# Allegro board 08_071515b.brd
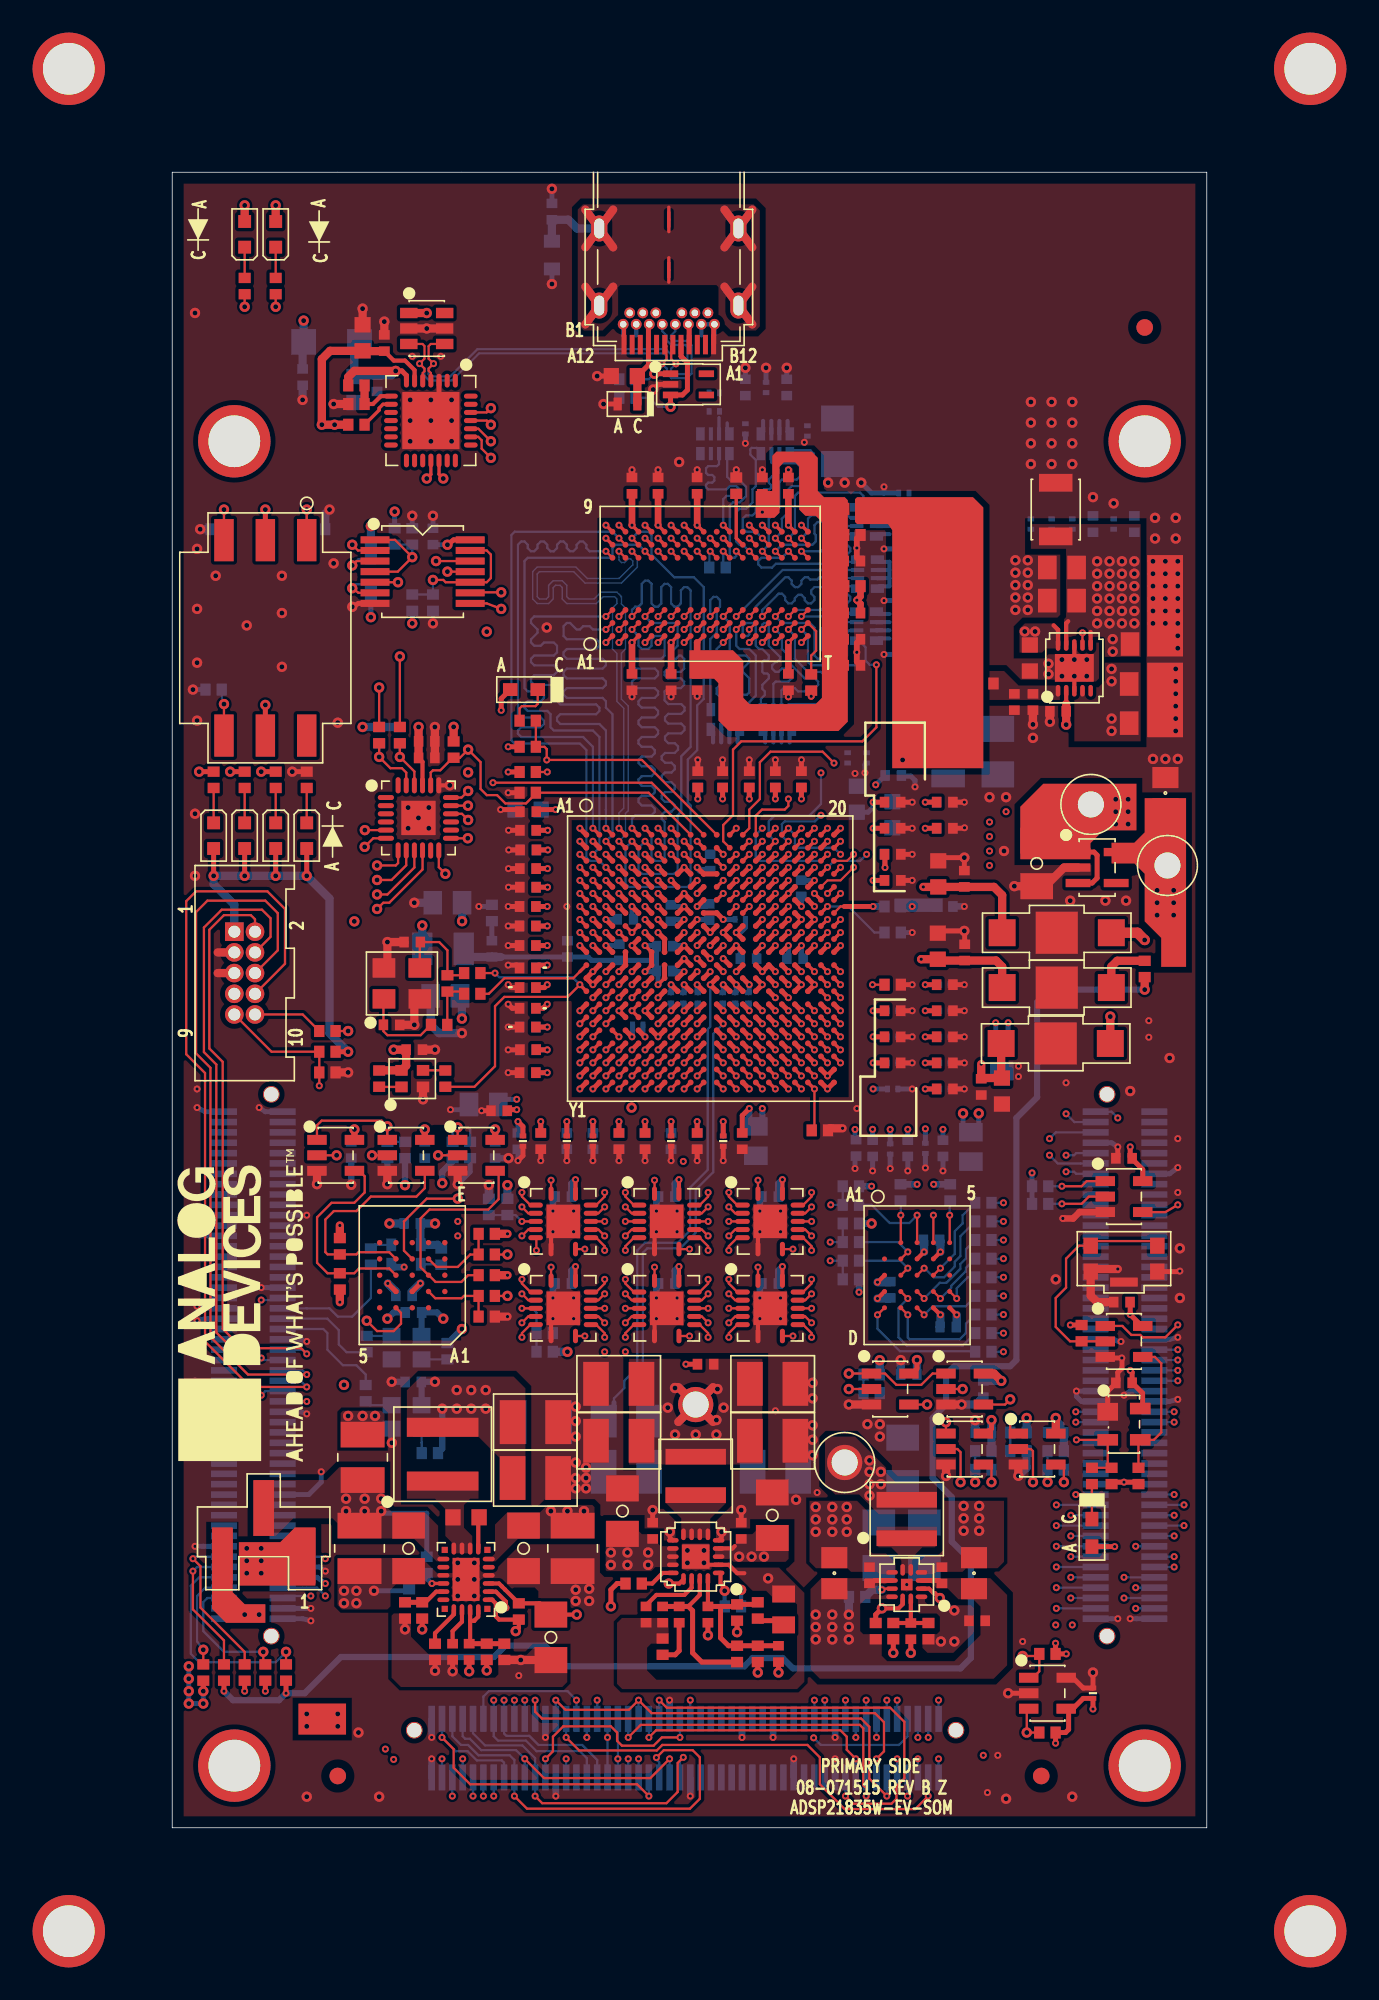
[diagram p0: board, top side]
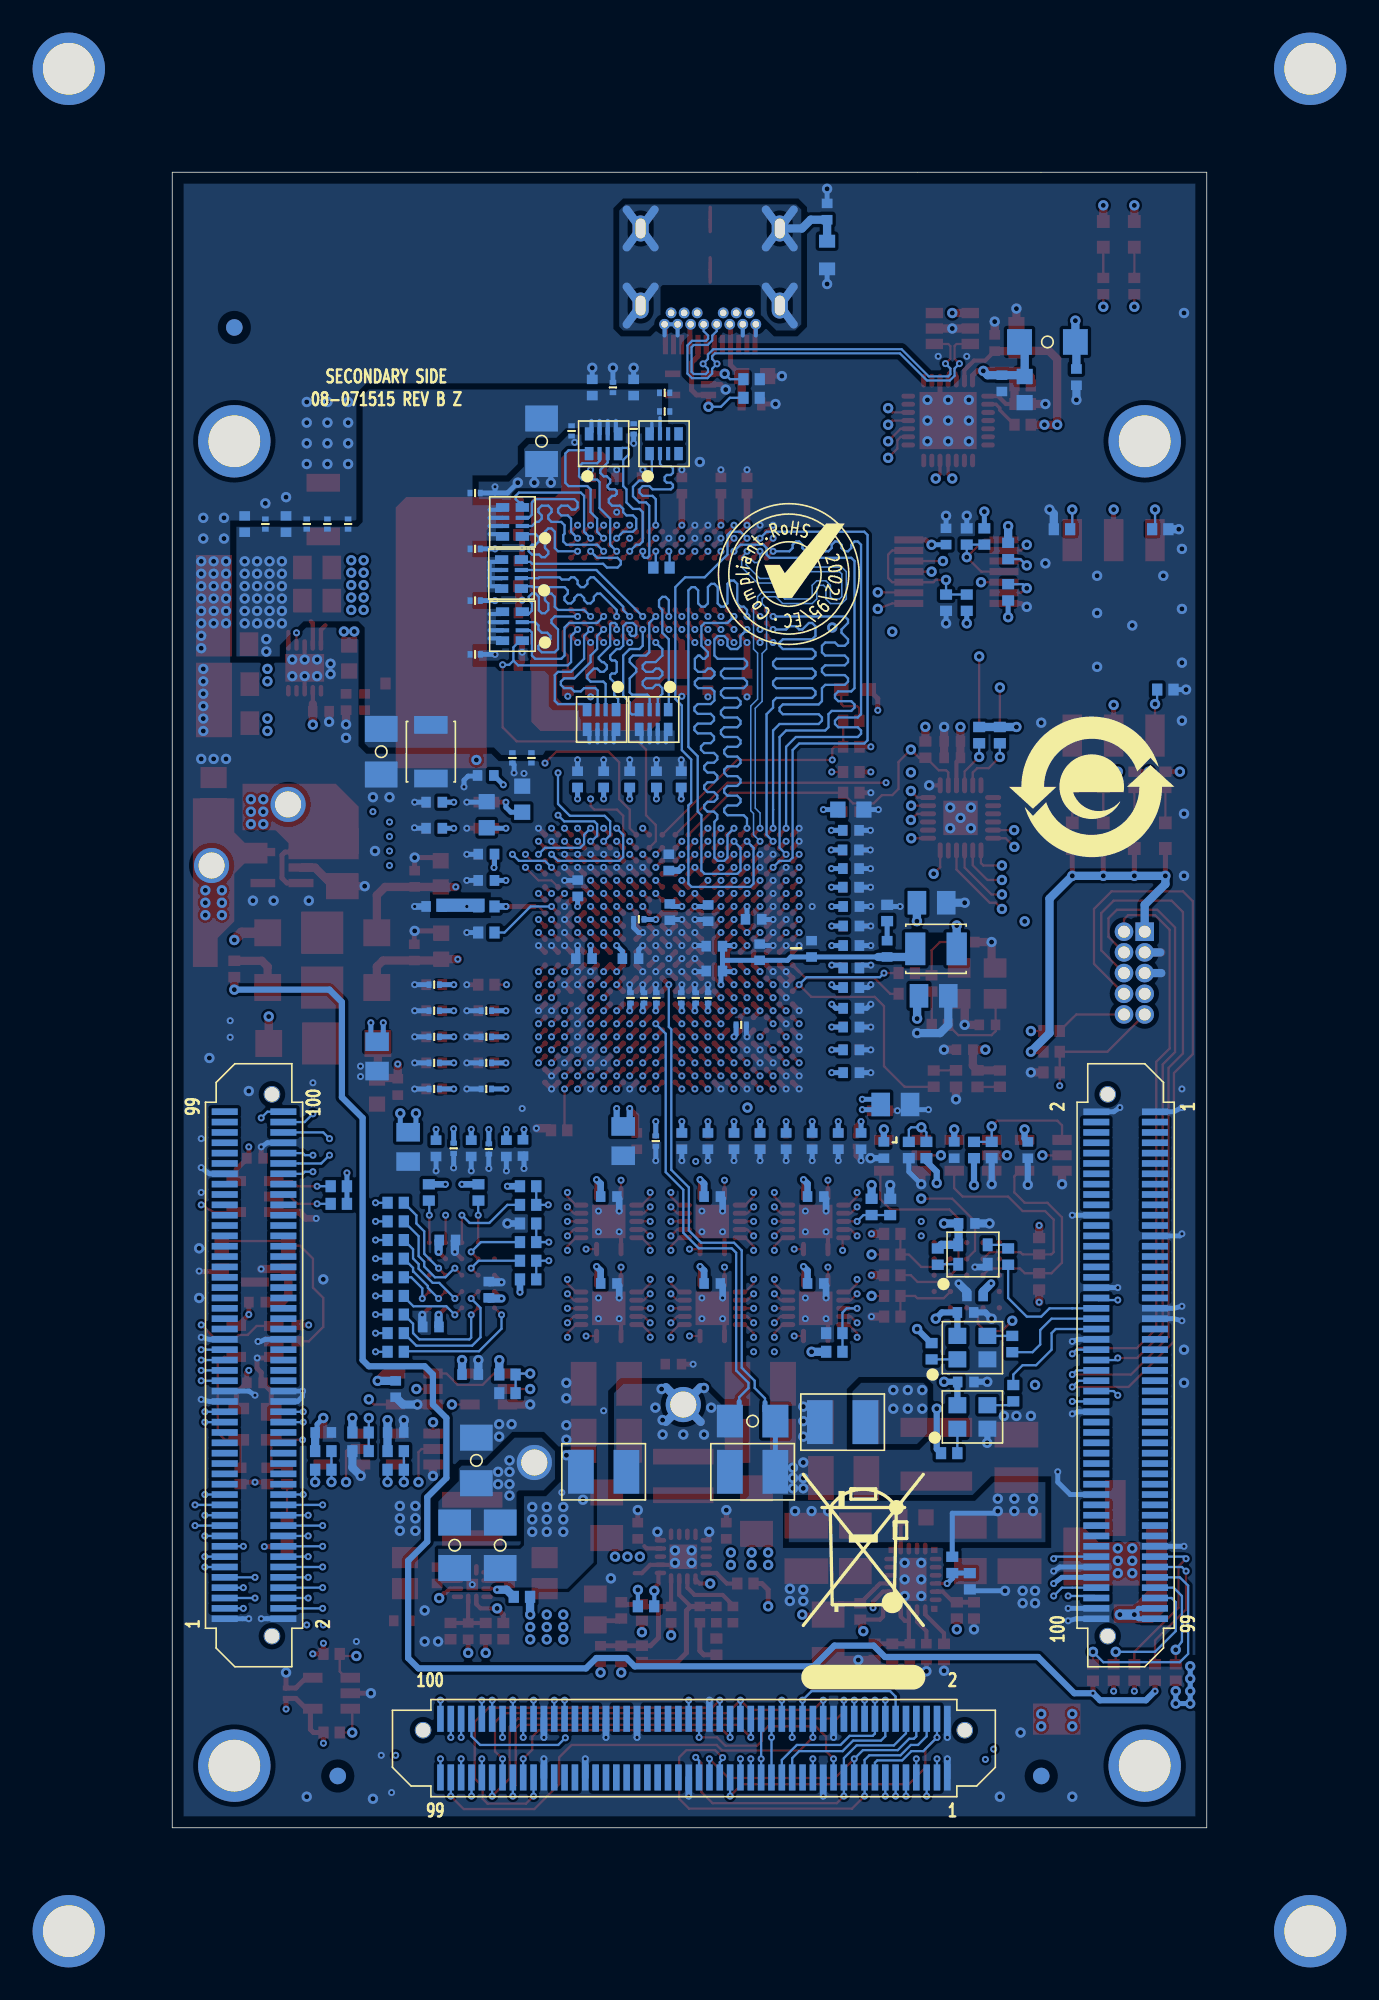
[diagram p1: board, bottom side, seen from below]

Outline 63.5 x 101.6 mm; copper layers: TOP, L2_PWR, L3_GND, L4_SIG, L5_SIG, L6_PWR, L7_SIG, L8_SIG, L9_GND, BOTTOM. Coordinates in mm from the lower left corner of the outline.
Outline path: 0,101.6 0,0 63.5,0 63.5,101.6 0,101.6

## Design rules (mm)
constraint set DEFAULT: min track width 0.14
net group DP_USB: nets USB_DM USB_DP
net group ADDRESS: nets DMC0_A00 DMC0_A01 DMC0_A02 DMC0_A03 DMC0_A04 DMC0_A05 DMC0_A06 DMC0_A07 DMC0_A08 DMC0_A09 DMC0_A10 DMC0_A11 DMC0_A12 DMC0_A13 DMC0_A14 DMC0_A15 DMC0_BA0 DMC0_BA1 DMC0_BA2 DMC0_CAS* DMC0_CKE DMC0_CS0* DMC0_ODT DMC0_RAS* DMC0_RESET* DMC0_WE*
net group DIGITAL: nets DMC0_CK DMC0_CK* DMC0_DQ00 DMC0_DQ01 DMC0_DQ02 DMC0_DQ03 DMC0_DQ04 DMC0_DQ05 DMC0_DQ06 DMC0_DQ07 DMC0_DQ08 DMC0_DQ09 DMC0_DQ10 DMC0_DQ11 DMC0_DQ12 DMC0_DQ13 DMC0_DQ14 DMC0_DQ15 DMC0_LDM DMC0_LDQS DMC0_LDQS* DMC0_UDM DMC0_UDQS DMC0_UDQS*

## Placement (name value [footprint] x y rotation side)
C1  0.1uF  [C0402]  28.22 82.37 90 top
C2  0.1uF  [C0402]  32.22 82.37 90 top
C3  0.1uF  [C0402]  37.82 82.37 90 top
C4  100pF  [C0402]  47.42 56.54 0 bottom
C5  0.1uF  [C0402]  29.82 82.37 90 top
C6  0.1uF  [C0402]  28.22 70.31 270 top
C7  0.1uF  [C0402]  30.62 70.31 270 top
C8  0.1uF  [C0402]  37.82 70.31 270 top
C9  0.01uF  [C0201]  44.91 81.92 180 bottom
C10  0.01uF  [C0201]  35.18 85.85 270 bottom
C11  10uF  [C0805H55]  59.64 67.79 0 top
C12  0.01uF  [C0201]  42.62 65.66 270 bottom
C13  10uF  [C0805H55]  59.64 70.19 0 top
C14  0.01uF  [C0201]  44.91 72.01 180 bottom
C15  4.7uF  [C1206H71]  50.67 66.04 270 bottom
C16  0.01uF  [C0201]  44.91 78.49 180 bottom
C17  4.7uF  [C1206H71]  40.83 85.09 270 bottom
C18  0.01uF  [C0201]  44.91 75.31 180 bottom
C19  100uF  [C1210H106]  47.62 66.04 270 bottom
C20  100uF  [C1210H106]  54.23 80.9 90 top
C21  0.01uF  [C0201]  38.99 85.73 270 bottom
C22  10uF  [C0805H55]  54.61 77.34 180 top
C23  0.01uF  [C0201]  41.45 65.66 270 bottom
C24  10uF  [C0805H55]  54.61 75.31 180 top
C25  0.01uF  [C0201]  33.27 88.06 180 bottom
C26  10uF  [C0805H55]  59.69 72.64 0 top
C27  1uF  [C0402]  52.83 69.09 270 top
C28  0.01uF  [C0402]  36.22 82.37 90 top
C29  0.01uF  [C0201]  33.27 86.92 180 bottom
C30  0.1uF  [C0402]  41.75 71.34 0 top
C31  0.01uF  [C0201]  52.71 80.01 90 bottom
C32  0.01uF  [C0402]  32.22 70.31 270 top
C33  0.01uF  [C0201]  55.25 80.01 90 bottom
C34  0.1uF  [C0402]  41.75 72.94 0 top
C35  0.01uF  [C0201]  57.79 80.01 90 bottom
C36  0.1uF  [C0402]  51.69 69.09 270 top
C37  0.1uF  [C0402]  59.05 80.01 90 bottom
C38  4.7uF  [C0603]  52.64 71.79 270 top
C39  0.1uF  [C0402]  41.75 74.55 180 top
C40  0.1uF  [C0402]  41.75 77.74 0 top
C41  1uF  [C0402]  56.52 80.01 90 bottom
C42  0.1uF  [C0402]  37.72 88.39 90 bottom
C43  1uF  [C0402]  35.18 88.39 90 bottom
C44  10uF  [C0603]  46.99 54.1 90 top
C45  0.1uF  [C0402]  48.64 53.72 90 top
C46  0.01uF  [C0402]  27.44 53.73 90 bottom
C47  0.1uF  [C0402]  19.62 53.94 90 bottom
C48  1uF  [C0402]  44.22 59.75 0 bottom
C49  10uF  [C0805H55]  49.02 41.78 270 bottom
C50  10uF  [C0805H55]  16.76 51.05 180 bottom
C51  1uF  [C0402]  21.82 54.14 180 bottom
C52  10uF  [C0805H55]  35.82 42.14 270 bottom
C53  1uF  [C0402]  32.26 64.34 90 bottom
C54  10uF  [C0805H55]  19.11 44.39 180 bottom
C55  10uF  [C0805H55]  16.89 56.77 180 bottom
C56  1uF  [C0402]  21.82 55.34 180 bottom
C57  10uF  [C0805H55]  50.93 47.34 270 bottom
C58  0.22uF  [C0402]  37.02 64.34 90 bottom
C59  0.47uF  [C0402]  41.97 41.72 270 bottom
C60  0.22uF  [C0402]  21.84 57.72 180 top
C61  1uF  [C0402]  21.82 51.56 180 bottom
C62  0.1uF  [C0402]  44.22 46.94 0 top
C63  0.22uF  [C0402]  44.26 64.58 0 bottom
C64  0.01uF  [C0201]  25.82 42.14 270 top
C65  0.22uF  [C0402]  27.81 55.75 180 bottom
C66  1uF  [C0402]  21.82 50.29 180 bottom
C67  0.1uF  [C0402]  47.42 50.14 0 top
C68  0.1uF  [C0402]  21.84 61.21 180 bottom
C69  0.22uF  [C0402]  35.42 64.34 90 top
C70  0.01uF  [C0201]  30.62 42.14 270 top
C71  0.22uF  [C0402]  21.82 46.34 180 bottom
C72  0.1uF  [C0402]  47.42 46.94 0 top
C73  0.1uF  [C0402]  21.84 61.21 180 top
C74  0.22uF  [C0402]  44.22 58.14 0 top
C75  0.1uF  [C0402]  22.62 42.14 270 bottom
C76  0.22uF  [C0402]  38.61 57.66 90 bottom
C77  0.1uF  [C0402]  47.42 51.74 0 top
C78  0.1uF  [C0402]  21.84 47.75 180 top
C79  0.22uF  [C0402]  37.02 64.34 90 top
C80  0.01uF  [C0201]  21.53 42.14 270 top
C81  0.22uF  [C0402]  21.84 58.86 180 top
C82  0.1uF  [C0402]  44.22 48.54 0 top
C83  0.1uF  [C0402]  21.82 51.56 180 top
C84  0.22uF  [C0402]  38.62 64.34 90 top
C85  0.01uF  [C0201]  46.23 41.7 270 bottom
C86  0.01uF  [C0201]  35.37 50.93 90 bottom
C87  0.1uF  [C0402]  47.42 45.34 0 top
C88  0.1uF  [C0402]  21.82 46.34 180 top
C89  0.1uF  [C0402]  44.22 58.14 0 bottom
C90  0.47uF  [C0402]  33.02 59.25 90 bottom
C91  0.1uF  [C0402]  21.82 55.34 180 top
C92  0.01uF  [C0201]  47.42 51.74 0 bottom
C93  0.1uF  [C0402]  35.37 53.34 180 bottom
C94  1000pF  [C0603]  44.2 62.17 90 bottom
C95  0.47uF  [C0402]  30.62 42.14 270 bottom
C96  0.1uF  [C0402]  21.82 54.14 180 top
C97  0.01uF  [C0201]  44.22 45.34 0 bottom
C98  0.1uF  [C0402]  38.62 64.34 90 bottom
C99  0.47uF  [C0402]  25.82 42.14 270 bottom
C100  0.1uF  [C0402]  21.82 52.77 180 top
C101  0.01uF  [C0201]  47.42 46.94 0 bottom
C102  1000pF  [C0603]  42.02 63.12 90 bottom
C103  0.47uF  [C0402]  21.22 42.14 270 bottom
C104  0.1uF  [C0402]  21.82 49.14 180 top
C105  0.01uF  [C0201]  47.42 50.14 0 bottom
C106  0.22uF  [C0402]  47.42 62.94 0 bottom
C107  0.01uF  [C0201]  44.07 41.66 270 bottom
C108  0.01uF  [C0201]  31.37 50.93 90 bottom
C109  0.1uF  [C0402]  34.99 42.14 270 top
C110  0.47uF  [C0402]  33.78 64.34 90 top
C111  0.47uF  [C0402]  45.15 41.7 270 bottom
C112  0.1uF  [C0402]  38.23 53.34 0 bottom
C113  0.01uF  [C0201]  44.22 50.14 0 bottom
C114  0.47uF  [C0402]  47.42 61.34 0 bottom
C115  0.47uF  [C0402]  47.31 41.7 270 bottom
C116  0.47uF  [C0402]  21.82 56.54 180 top
C117  0.01uF  [C0201]  33.82 42.14 270 bottom
C118  0.1uF  [C0402]  33.78 64.34 90 bottom
C119  0.47uF  [C0402]  42.99 41.7 270 bottom
C120  0.47uF  [C0402]  21.85 60.01 180 top
C121  0.01uF  [C0201]  44.22 46.94 0 bottom
C122  0.1uF  [C0402]  30.61 56.13 270 bottom
C123  0.22uF  [C0402]  29.02 42.14 270 bottom
C124  0.47uF  [C0402]  21.82 56.54 180 bottom
C125  0.01uF  [C0201]  47.42 45.34 0 bottom
C126  0.22uF  [C0402]  21.84 62.36 180 top
C127  0.01uF  [C0201]  24.22 42.14 270 top
C128  0.01uF  [C0201]  33.78 50.93 90 bottom
C129  0.1uF  [C0402]  47.42 48.54 0 top
C130  0.47uF  [C0402]  47.42 62.94 0 top
C131  0.22uF  [C0402]  24.22 42.14 270 bottom
C132  0.01uF  [C0201]  32.26 50.93 90 bottom
C133  0.1uF  [C0402]  44.22 50.14 0 top
C134  0.1uF  [C0402]  44.22 61.34 0 top
C135  0.22uF  [C0402]  29.02 42.14 270 top
C136  0.01uF  [C0201]  34.54 50.93 90 bottom
C137  0.01uF  [C0201]  34.86 55.75 0 bottom
C138  0.1uF  [C0402]  44.22 59.74 0 top
C139  0.22uF  [C0402]  32.22 42.14 270 top
C140  0.47uF  [C0402]  21.82 52.77 180 bottom
C141  0.01uF  [C0201]  47.42 48.54 0 bottom
C142  0.1uF  [C0402]  35.42 64.34 90 bottom
C143  0.22uF  [C0402]  27.42 42.14 270 top
C144  0.47uF  [C0402]  21.84 58.86 180 bottom
C145  0.01uF  [C0201]  44.22 48.54 0 bottom
C146  0.22uF  [C0402]  47.42 61.34 0 top
C147  0.01uF  [C0201]  28.57 49.28 180 bottom
C148  0.47uF  [C0402]  21.82 47.74 180 bottom
C149  0.01uF  [C0201]  33.82 42.14 270 top
C150  0.47uF  [C0402]  32.26 64.34 90 top
C151  0.22uF  [C0402]  27.42 42.14 270 bottom
C152  0.01uF  [C0201]  30.61 50.93 90 bottom
C153  0.1uF  [C0402]  44.22 62.94 0 top
C154  0.22uF  [C0402]  32.22 42.14 270 bottom
C155  0.47uF  [C0402]  21.85 60.01 180 bottom
C156  0.1uF  [C0402]  32.96 56.2 270 bottom
C157  0.22uF  [C0402]  20.07 44.01 180 top
C158  4.7uF  [C0603]  27.75 89.09 180 top
C159  0.01uF  [C0402]  45.21 27.81 180 bottom
C160  0.01uF  [C0402]  49.78 26.92 270 bottom
C161  0.47uF  [C0402]  21.82 49.14 180 bottom
C162  1000pF  [C0603]  21.84 62.48 180 bottom
C163  0.22uF  [C0402]  22.62 42.14 270 top
C164  0.47uF  [C0402]  21.82 50.29 180 top
C165  0.47uF  [C0402]  21.84 57.72 180 bottom
C166  27pF  [C0402]  13.46 49.28 0 top
C168  27pF  [C0402]  14.73 54.36 180 top
C170  0.01uF  [C0402]  49.78 24.26 180 bottom
C171  0.01uF  [C0402]  54.23 24.26 180 bottom
C172  0.1uF  [C0402]  46.61 36.07 0 bottom
C173  0.01uF  [C0402]  15.5 41.59 270 bottom
C174  0.01uF  [C0402]  10.99 41.59 270 bottom
C175  0.01uF  [C0402]  19.82 41.59 270 bottom
C176  0.01uF  [C0402]  14.22 32.64 0 bottom
C177  10uF  [C0603]  47.02 58.54 90 top
C178  0.1uF  [C0402]  48.62 58.24 90 top
C179  0.1UF  [C0402]  15.62 66.67 0 top
C180  0.01uF  [C0402]  58.42 41.08 180 top
C181  0.01uF  [C0402]  58.29 32.26 180 top
C182  0.01uF  [C0402]  58.42 27.3 180 top
C183  0.1uF  [C0402]  8 89.03 270 bottom
C184  0.01uF  [C0402]  23.3 99.19 90 bottom
C185  4.7uF  [C0603]  11.18 88.27 270 bottom
C186  0.1uF  [C0402]  12.57 88.65 270 bottom
C187  4.7uF  [C0603]  11.68 91.44 90 top
C188  0.1uF  [C0402]  13.02 91.12 90 top
C189  0.01uF  [C0402]  16 79.25 90 bottom
C190  10uF  [C1210-2]  11.68 22.73 90 top
C191  0.22uF  [C0402]  34.92 18.22 90 top
C192  0.22uF  [C0402]  29.49 18.22 90 top
C193  3.3pF  [C0402]  30.1 13.08 270 top
C194  22uF  [C1206H71]  27.64 19.43 90 top
C195  270pF  [C0402]  31.11 13.08 270 top
C196  1uF  [C1206H71]  14.51 17.14 270 top
C197  22uF  [C1206H71]  36.83 19.18 90 top
C198  1uF  [C1206H71]  21.56 17.14 270 top
C199  0.1uF  [C0402]  44.07 33.02 270 bottom
C200  0.1uF  [C0402]  47.62 30.73 180 bottom
C201  0.1uF  [C0402]  14.86 47.75 0 top
C202  0.1uF  [C0402]  29.08 13.08 270 top
C203  10uF  [C1210-2]  11.49 17.14 270 top
C204  1500pF  [C0402]  17.21 10.79 270 top
C205  10uF  [C1210-2]  24.57 17.14 270 top
C206  1uF  [C1206H71]  23.24 11.68 270 top
C207  0.1uF  [C0603]  18.03 19.05 180 top
C208  100pF  [C0402]  32.88 13.08 90 top
C209  100pF  [C0402]  37.21 10.67 270 top
C210  47pF  [C0402]  18.22 10.79 90 top
C211  47uF  [C1210H95]  27.41 23.75 180 top
C212  1uF  [C1206H71]  27.88 24.96 180 bottom
C213  47uF  [C1210H95]  22.29 21.46 0 top
C214  47uF  [C1210H95]  27.41 27.24 180 top
C215  0.1uF  [C0402]  47.24 15.49 90 top
C216  47uF  [C1210H95]  22.29 24.89 0 top
C217  47uF  [C1210H95]  36.86 23.75 0 top
C218  0.1uF  [C0402]  42.8 15.49 90 top
C219  47uF  [C1210H95]  22.35 24.89 0 bottom
C220  2.2pF  [C0402]  45.33 12.07 90 top
C221  47uF  [C1210H95]  27.88 21.84 180 bottom
C222  4.7uF  [C0805H60]  40.64 15.62 90 top
C223  47uF  [C1210H95]  37.02 21.84 0 bottom
C224  22uF  [C1206H71]  46.16 17.34 270 bottom
C225  4.7uF  [C0805H60]  49.21 15.62 90 top
C226  47uF  [C1210H95]  36.86 27.24 0 top
C227  22uF  [C1206H71]  44.83 22.54 90 bottom
C228  1uF  [C1206H71]  53.06 59.18 270 top
C229  0.1uF  [C0402]  32.74 28.45 180 top
C230  22uF  [C1206H71]  43.37 17.34 270 bottom
C231  4.7uF  [C0805H60]  60.96 63.5 90 top
C232  0.01UF  [C0402]  15.62 65.66 0 top
C233  0.1uF  [C0402]  24 38.73 0 bottom
C234  0.1uF  [C0402]  24 33.4 0 bottom
C235  0.1uF  [C0402]  30.35 38.73 0 bottom
C236  0.1uF  [C0402]  30.35 33.4 0 bottom
C237  0.1uF  [C0402]  36.7 38.73 0 bottom
C238  0.1uF  [C0402]  36.7 33.4 0 bottom
C239  10uF  [C0603]  50.93 45.21 270 top
C240  0.1uF  [C0402]  49.66 45.47 270 top
C242  0.1uF  [C0402]  30.23 54.1 0 bottom
C243  0.1uF  [C0402]  24.26 53.94 90 bottom
C244  0.01uF  [C0402]  30.23 52.58 0 bottom
C245  0.01uF  [C0201]  53.98 80.01 90 bottom
C246  0.01uF  [C0201]  36.45 88.39 90 bottom
C247  0.01uF  [C0201]  56.52 8.26 90 top
C248  0.1uF  [C0402]  49.4 12.7 180 top
C251  0.1uF  [C0402]  14.73 37.08 180 bottom
C252  0.1uF  [C0402]  14.81 31.62 180 bottom
C253  0.1uF  [C0402]  14.79 27.36 180 bottom
C254  1uF  [C0402]  54.37 68.52 180 top
D1  ESDA6V1SC6Y  [SOT23_6-3]  15.62 92.01 270 top
D15  ESDA25P35-1U1M  [DFN2_1_6X1]  27.95 87.38 180 top
D17  ESDA25W5  [SC70-5_A]  31.69 88.58 270 top
DS1  SML-D13FWT86C  [LED0603-2]  6.35 60.88 270 top
DS2  SML-D13FWT86C  [LED0603-2]  4.45 60.88 270 top
DS3  SML-D13FWT86C  [LED0603-2]  2.54 60.88 270 top
DS4  SML-D13FWT86C  [LED0603-2]  8.26 60.88 270 top
DS5  SML-D14U2WT86C  [LED0603_A]  56.45 18.1 270 top
DS6  SML-D14U2WT86C  [LED0603_A]  21.59 69.85 180 top
DS7  LY L296-Q2R2-26-Z  [LED0603-2]  4.45 97.79 90 top
DS8  LY L296-Q2R2-26-Z  [LED0603-2]  6.35 97.79 90 top
E1  600OHM  [L1206]  9.78 91.19 0 bottom
FL1  4700pF  [F2606]  54.29 51.56 180 top
FL2  4700pF  [F2606]  54.29 54.93 180 top
FL3  4700pF  [F2606]  54.23 48.13 180 top
J1  LSS-150-01-L-DV-A-K  [CNSAMTECLSS-150-01-X-DV-A]  58.48 28.39 90 bottom
J2  LSS-150-01-L-DV-A-K  [CNSAMTECLSS-150-01-X-DV-A]  31.48 4.88 0 bottom
J3  LSS-150-01-L-DV-A-K  [CNSAMTECLSS-150-01-X-DV-A]  4.98 28.39 270 bottom
JP1  TSM-103-01-H-SV  [CNSMMHDR1X3L300W100H403]  5.61 18.16 180 top
L1  10UH  [L1210H67]  16.62 53.94 0 bottom
L2  0.1UH  [LSMSQ157H122]  32.13 21.59 90 top
L3  1uH  [LSML208W216H122]  16.6 22.92 90 top
L4  220NH  [LSMSQ157H83_A]  45.09 18.95 90 top
NOREF  -  []  76.2 -12.7 90 top
NOREF#2  -  []  -111.76 -130.81 0 top
NOREF#3  -  []  134.68 145.73 0 top
NOREF#4  -  []  4.19 32.07 90 top
NOREF#5  -  [unnamed#2]  59.69 85.09 0 top
NOREF#6  -  []  -12.7 101.6 0 top
NOREF#7  -  []  -209.55 -209.55 0 top
NOREF#8  -  []  63.5 0 0 top
NOREF#9  -  []  -12.7 0 0 top
NOREF#10  -  [unnamed#2]  10.16 3.17 0 top
NOREF#11  -  []  -111.76 -130.81 0 top
NOREF#12  -  []  3.81 3.81 0 top
NOREF#13  -  [unnamed#2]  69.85 -6.35 0 top
NOREF#14  -  []  17.3 -86.01 0 top
NOREF#15  -  []  76.2 -12.7 0 top
NOREF#16  -  []  42.93 2.1 270 top
NOREF#17  -  [unnamed#2]  53.34 3.17 0 top
NOREF#18  -  []  0 0 0 top
NOREF#19  -  []  -12.7 -12.7 0 top
NOREF#20  -  []  34.67 -51.88 0 top
NOREF#21  -  []  3.81 3.81 0 top
NOREF#22  -  []  168.21 89.28 0 top
NOREF#23  -  []  0 0 0 top
NOREF#24  -  [unnamed#2]  -6.35 107.95 0 top
NOREF#25  -  []  0 -12.7 0 top
NOREF#26  -  []  -18.73 11.3 0 top
NOREF#27  -  []  63.5 -12.7 0 top
NOREF#28  -  []  0 101.6 0 top
NOREF#29  -  [unnamed#2]  59.69 92.08 0 top
NOREF#30  -  [unnamed#2]  59.69 3.81 0 top
NOREF#31  -  [unnamed#2]  3.81 3.81 0 top
NOREF#32  -  [unnamed#2]  69.85 107.95 0 top
NOREF#33  -  []  -12.7 114.3 0 top
NOREF#34  -  [unnamed#2]  3.81 85.09 0 top
NOREF#35  -  []  93.34 193.29 0 top
NOREF#36  -  []  -12.7 114.3 0 top
NOREF#37  -  []  52.2 -18.73 90 top
NOREF#38  -  []  11.3 120.33 270 top
NOREF#39  -  []  -111.76 -130.81 0 top
NOREF#40  -  []  -111.76 -130.81 0 top
NOREF#41  -  [unnamed#2]  -6.35 -6.35 0 top
NOREF#42  -  []  16.99 -82.2 0 top
NOREF#43  -  []  276.66 378.88 0 top
NOREF#44  -  []  82.23 90.3 180 top
NOREF#45  -  []  -12.7 -12.7 0 top
NOREF#46  -  []  7.06 63.88 180 bottom
NOREF#47  -  [unnamed#2]  59.69 92.08 180 bottom
NOREF#48  -  []  25.65 76.94 180 bottom
NOREF#49  -  []  11.81 25.37 180 bottom
NOREF#50  -  [unnamed#2]  10.16 3.17 180 bottom
NOREF#51  -  [unnamed#2]  53.34 3.17 180 bottom
P1  632723300011  [CNWURTH632723300011]  30.48 95.6 180 top
P6  SHF-105-01-L-D-TH-TR  [CNTHMHDR2X5L500W200H215]  3.81 54.99 270 top
R1  34  [R0402]  44.22 54.94 0 bottom
R2  2K  [R0402]  44.22 56.54 180 bottom
R3  200  [R0402]  33.47 77.34 0 bottom
R4  240  [R0402]  34.62 82.37 90 top
R5  0  [R0402]  42.04 14.17 0 bottom
R6  5.1K  [R0402]  27.94 87.76 180 bottom
R7  0  [R0402]  49.91 70.22 180 top
R8  10K  [R0402]  39.22 70.29 90 top
R9  1K  [R0402]  41.75 76.2 180 top
R10  1K  [R0402]  41.75 79.34 0 top
R11  1K  [R0402]  41.75 80.94 0 top
R12  100  [R0402]  49.78 21.97 180 bottom
R13  100  [R0402]  54.23 21.97 180 bottom
R14  2.2K  [R0402]  49.78 23.11 180 bottom
R15  2.2K  [R0402]  54.23 23.11 180 bottom
R16  0  [R0402]  59.69 52.71 90 top
R17  20  [R0402]  19.62 56.14 90 bottom
R18  0  [R0402]  18.41 51.18 180 top
R19  100K  [R0402]  42.93 27.81 180 bottom
R20  1.2K  [R0402]  16.38 49.28 180 top
R21  100K  [R0402]  42.93 26.67 0 bottom
R22  499K  [R0402]  16.89 51.82 90 top
R23  10K  [R0402]  39.75 42.8 0 top
R24  10K  [R0402]  8.89 79.69 0 bottom
R25  10K  [R0402]  2.54 69.85 180 bottom
R26  10K  [R0402]  2.86 79.69 180 bottom
R27  0  [R0402]  18.41 52.45 0 top
R29  100  [R0402]  13.97 67.06 270 top
R30  100  [R0402]  12.7 67.06 270 top
R31  2.2K  [R0402]  13.97 67.06 270 bottom
R32  2.2K  [R0402]  12.7 67.06 270 bottom
R33  100K  [R0402]  51.94 24.26 180 bottom
R34  100K  [R0402]  51.94 23.11 0 bottom
R35  100K  [R0402]  20.57 38.1 270 bottom
R36  20K  [R0402]  19.43 38.1 90 bottom
R37  100K  [R0402]  22.86 29.21 180 bottom
R38  100K  [R0402]  22.86 30.35 0 bottom
R39  10K  [R0402]  41.66 33.66 0 bottom
R40  10K  [R0402]  41.66 39.37 0 bottom
R41  0  [R0402]  4.45 9.53 90 top
R42  0  [R0402]  3.17 9.53 90 top
R43  0  [R0402]  6.98 9.53 90 top
R44  0  [R0402]  1.91 9.53 90 top
R45  0  [R0402]  5.71 9.53 90 top
R46  10K  [R0402]  19.3 33.91 180 top
R47  10K  [R0402]  10.29 35.69 270 top
R48  10K  [R0402]  10.29 33.53 90 top
R49  33  [R0402]  19.3 32.64 180 top
R50  10K  [R0402]  19.3 31.37 0 top
R51  10K  [R0402]  19.3 36.45 180 top
R52  33  [R0402]  19.3 35.18 0 top
R53  100K  [R0402]  14.29 41.59 90 bottom
R54  20K  [R0402]  13.2 41.59 270 bottom
R55  100K  [R0402]  17.21 41.59 90 bottom
R56  20K  [R0402]  18.29 41.59 270 bottom
R57  10K  [R0402]  21.82 63.52 180 top
R58  0  [R0402]  44.22 51.74 180 top
R59  330  [R0402]  21.82 67.94 0 top
R60  10K  [R0402]  21.82 66.34 0 top
R61  10K  [R0402]  21.82 64.79 0 top
R62  10K  [R0402]  53.28 38.29 0 bottom
R63  10K  [R0402]  53.28 39.37 0 bottom
R64  10K  [R0402]  17.27 66.17 270 top
R65  22.1K  [R0402]  11.3 88.52 0 top
R66  5.1K  [R0402]  27.94 88.9 180 bottom
R67  10K  [R0402]  41.66 37.08 180 bottom
R68  0  [R0402]  41.66 34.8 0 bottom
R69  0  [R0402]  41.66 38.23 0 bottom
R70  10K  [R0402]  55.82 30.35 270 top
R71  10K  [R0402]  59.31 21.59 90 top
R72  330  [R0402]  2.54 64.31 90 top
R73  330  [R0402]  56.45 21.59 90 top
R74  330  [R0402]  4.45 64.31 90 top
R75  10K  [R0402]  57.66 21.59 90 top
R76  330  [R0402]  6.35 64.31 90 top
R77  330  [R0402]  8.26 64.31 90 top
R78  10K  [R0402]  9.53 47.62 180 top
R79  10K  [R0402]  9.53 46.36 0 top
R80  1MEG  [R0603]  23.3 96.52 270 bottom
R81  100K  [R0402]  14.73 75.18 90 bottom
R82  100K  [R0402]  16 75.18 270 bottom
R83  100K  [R0402]  13.65 79.25 270 bottom
R84  100K  [R0402]  14.73 79.25 90 bottom
R85  0  [R0402]  9.53 48.9 0 top
R86  10K  [R0402]  12.19 78.36 270 bottom
R87  10K  [R0402]  12.19 75.82 90 bottom
R88  47.5K  [R0402]  11.3 87.38 180 top
R89  330  [R0402]  4.45 94.62 270 top
R90  330  [R0402]  6.35 94.62 270 top
R91  37.4K  [R0402]  30.1 11.11 90 top
R92  0  [R0402]  34.42 13.59 180 bottom
R93  0  [R0402]  14.29 13.34 270 top
R94  0  [R0402]  15.34 13.34 270 top
R95  38.3K  [R0402]  14.54 15.13 90 bottom
R96  100K  [R0402]  15.62 16.13 270 bottom
R97  1.69MEG  [R0402]  34.67 10.67 90 top
R98  15.8K  [R0402]  16.13 10.79 270 top
R99  100K  [R0402]  28.32 14.99 180 top
R100  100K  [R0402]  21.27 13.27 90 top
R101  100K  [R0402]  34.67 13.21 90 top
R102  91K  [R0402]  35.94 13.34 270 top
R103  9K  [R0805]  37.53 13.4 90 top
R104  100K  [R0402]  43.18 12.07 270 top
R105  100K  [R0402]  19.3 10.79 90 top
R106  41.2K  [R0402]  20.38 10.79 270 top
R107  100K  [R0402]  35.94 10.67 270 top
R108  100K  [R0402]  44.26 12.07 90 top
R109  56.2K  [R0402]  46.42 12.07 270 top
R110  33  [R0402]  41.66 35.94 0 bottom
R111  0  [R0402]  49.78 29.21 0 bottom
R112  0  [R0402]  49.78 31.5 0 bottom
R113  10K  [R0402]  12.7 45.97 270 top
R114  0  [R0402]  49.78 32.64 0 bottom
R115  0  [R0402]  49.78 33.78 0 bottom
R116  0  [R0402]  49.78 34.92 0 bottom
R117  0  [R0402]  49.78 38.35 0 bottom
R118  0  [R0402]  49.78 30.35 0 bottom
R119  0  [R0402]  49.78 36.07 0 bottom
R120  0  [R0402]  49.78 37.21 0 bottom
R121  10K  [R0402]  44.7 38.99 90 bottom
R122  10K  [R0402]  47.75 38.99 90 bottom
R123  33  [R0402]  16.76 45.97 270 top
R124  10K  [R0402]  11.3 86.11 0 top
R136  3.3K  [R0402]  53.72 10.67 180 top
R137  3.3K  [R0402]  53.72 5.84 180 top
R139  10K  [R0402]  16.51 35.05 270 bottom
R140  10K  [R0402]  16.89 29.24 270 bottom
R141  33  [R0402]  12.19 35.05 270 bottom
R142  33  [R0402]  11.94 29.68 270 bottom
R143  10K  [R0402]  15.81 22.99 180 bottom
R144  33  [R0402]  11.87 26.67 90 bottom
RN1  100  [RESNET8]  42.68 76.94 90 bottom
RN2  100  [RESNET8]  42.62 73.74 90 bottom
RN3  100  [RESNET8]  42.62 80.14 90 bottom
RN4  100  [RESNET8]  37.02 84.94 180 bottom
RN5  100  [RESNET8]  37.15 68.01 0 bottom
RN6  100  [RESNET8]  33.95 68.01 0 bottom
RN7  100  [RESNET8]  33.31 84.94 180 bottom
S1  RDTAR10S1R  [SWSMSQ394H268]  5.71 73.03 180 top
S2  KMR223GLFG  [SWSML165W110H75-G]  58.42 34.92 0 top
TP1  WHT  [CNLOOPTP]  56.39 62.8 0 top
TP2  WHT  [CNLOOPTP]  32.13 25.97 0 top
TP3  WHT  [CNLOOPTP]  41.28 22.42 0 top
TP4  WHT  [CNLOOPTP]  61.09 59.05 0 top
U1  ADSP-21835-BPZENG  [CSPBGA400_17X17]  33.02 53.34 270 top
U2  MIC5166YML-TR  [DFN10_3X3_PAD2_4X1_7]  55.37 71.18 0 top
U3  74CBTLV1G125DBVRQ1  [SOT23-5L-2]  44.07 26.92 270 top
U4  IS25LP512M-RHLE  [TBGA24]  14.73 33.91 90 top
U5  74CBTLV1G125DBVRQ1  [SOT23-5L-2]  14.35 41.27 270 top
U7  PI3C3125LEX  [TSSOP14]  15.37 77.09 270 top
U8  IS43TR16256BL-107MBL  [BGA96_13X9]  33.02 76.34 0 top
U9  74CBTLV1G125DBVRQ1  [SOT23-5L-2]  18.67 41.27 270 top
U10  74CBTLV1G125DBVRQ1  [SOT23-5L-2]  10.03 41.27 270 top
U11  SN74LVC1G08QDBVRQ1  [SOT23-5L-2]  58.42 38.73 270 top
U13  SN74LVC1G08QDBVRQ1  [SOT23-5L-2]  58.42 29.84 270 top
U14  ADM6315-29D2ARTZR7  [SOT143A]  58.42 24.76 270 top
U15  CP2102N-A02-GQFN28  [QFN28_5X5_PAD3_5X3_5]  15.88 86.36 180 top
U16  LTC3310JV#WPBF  [QFN18_3X3_PAD1_51X1_7]  32.13 16.64 90 top
U17  LTC3307AHV#WTRMPBF  [QFN12_2X2_PAD0_7X0_7]  45.09 14.92 90 top
U18  ADP151AUJZ-1.8-R7  [TSOT-5]  56.77 58.93 270 top
U19  74CBTLV1G125DBVRQ1  [SOT23-5L-2]  48.64 26.92 270 top
U20  74CBTLV1G125DBVRQ1  [SOT23-5L-2]  48.64 23.24 270 top
U21  74CBTLV1G125DBVRQ1  [SOT23-5L-2]  53.09 23.24 270 top
U22  SN74CB3T3125RGYR  [QFN14_3_5X3_5_PAD2_05X2_05]  24 37.21 270 top
U23  SN74CB3T3125RGYR  [QFN14_3_5X3_5_PAD2_05X2_05]  24 31.88 270 top
U24  ADP5587ACPZ-1  [QFN24_4X4_PAD2_1X2_1]  15.11 61.98 270 top
U25  S71KL512SC0BHB003  [BGA24_8X6]  45.72 33.91 270 top
U26  24AA01T-I/OT  [SOT23-5L-2]  53.72 8.26 270 top
U27  SN74CB3T3125RGYR  [QFN14_3_5X3_5_PAD2_05X2_05]  30.35 37.21 270 top
U28  SN74CB3T3125RGYR  [QFN14_3_5X3_5_PAD2_05X2_05]  30.35 31.88 270 top
U29  SN74CB3T3125RGYR  [QFN14_3_5X3_5_PAD2_05X2_05]  36.7 37.21 270 top
U30  SN74CB3T3125RGYR  [QFN14_3_5X3_5_PAD2_05X2_05]  36.7 31.88 270 top
VR1  LT8636EV#WPBF  [LQFN20_4X3_PAD2_65X1_65]  18.03 15.24 90 top
Y1  25MEGHZ  [YSML126W98H31]  14.1 51.82 0 top
Y2  25MEGHZ  [YSML79W63H32]  14.73 45.97 0 top
Y4  24.576MEGHZ  [YSML79W63H31]  14.35 35.18 180 bottom
Y5  25MEGHZ  [YSML98W79H35]  14.38 29.46 180 bottom
Y6  25MEGHZ  [YSML98W79H35]  14.38 25.21 180 bottom

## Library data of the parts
C1-C3 C5-C8 C37 C42 C47 C62 C67 C68 C72 C73 C75 C77 C78 C82 C83 C87-C89 C91 C93 C96 C98 C100 C104 C112 C118 C122 C134 C138 C142 C153 C156 C201 C202 C215 C218 C229 C242 C243 C248 C251-C253 = CAP: User Part Number: UPN; Tolerance: 10; alternate symbols: (C0402L); part number: CAP_SM-0.1UF,25V,10,E033331,C0402; tolerance: 10
C4 = CAP: User Part Number: UPN; Tolerance: 5; alternate symbols: (C0402L); part number: CAP_SM-100PF,50V,5,E024302,C0402; tolerance: 5
C9 C10 C12 C14 C16 C18 C21 C23 C25 C29 C31 C33 C35 C64 C70 C80 C85 C86 C92 C97 C101 C105 C107 C108 C113 C117 C121 C125 C127 C128 C132 C136 C137 C141 C145 C147 C149 C152 C245-C247 = CAP: Tolerance: 10; User Part Number: UPN; alternate symbols: (C0201L); part number: CAP_SM-0.01UF,10V,10,E041205,C0201; tolerance: 10
C11 C13 C22 C24 C26 C49 C50 C52 C54 C55 C57 = CAP: User Part Number: UPN; Tolerance: 10; alternate symbols: (); part number: CAP_SM-10UF,16V,10,E040074,C0805H55; tolerance: 10
C15 C17 = CAP: Tolerance: 10; User Part Number: UPN; alternate symbols: (C1206H71L); part number: CAP_SM-4.7UF,50V,10,E033298,C1206H71; tolerance: 10
C19 C20 = CAP: Tolerance: 20; User Part Number: UPN; alternate symbols: (); part number: CAP_SM-100UF,6.3V,20,E034669,C1210H106; tolerance: 20
C27 C41 C43 C48 C51 C53 C56 C61 C66 C254 = CAP: User Part Number: UPN; Tolerance: 10; alternate symbols: (C0402L); part number: CAP_SM-1UF,10V,10,E028140,C0402; tolerance: 10
C28 C32 C46 C159 C160 C170 C171 C173-C176 C180-C182 C184 C189 C244 = CAP: User Part Number: UPN; Tolerance: 10; alternate symbols: (C0402L); part number: CAP_SM-0.01UF,25V,10,E030894,C0402; tolerance: 10
C30 C34 C36 C39 C40 C45 C109 C129 C133 C178 C183 C186 C188 C240 = CAP: User Part Number: UPN; Tolerance: 10; alternate symbols: (C0402L); part number: CAP_SM-0.1UF,16V,10,E028141,C0402; tolerance: 10
C38 C185 C187 = CAP: User Part Number: UPN; Tolerance: 10; alternate symbols: (C0603L); part number: CAP_SM-4.7UF,10V,10,E034981,C0603; tolerance: 10
C44 C177 C239 = CAP: User Part Number: UPN; Tolerance: 20; alternate symbols: (C0603L); part number: CAP_SM-10UF,10V,20,E033351,C0603; tolerance: 20
C58 C60 C63 C65 C69 C71 C74 C76 C79 C81 C84 C106 C123 C126 C131 C135 C139 C143 C146 C151 C154 C157 C163 = CAP: User Part Number: UPN; Tolerance: 10; alternate symbols: (C0402L); part number: CAP_SM-0.22UF,25V,10,E041210,C0402; tolerance: 10
C59 C90 C95 C99 C103 C110 C111 C114-C116 C119 C120 C124 C130 C140 C144 C148 C150 C155 C161 C164 C165 = CAP: User Part Number: UPN; Tolerance: 10; alternate symbols: (C0402L); part number: CAP_SM-0.47UF,10V,10,E035987,C0402; tolerance: 10
C94 C102 C162 = CAP: User Part Number: UPN; Tolerance: 5; alternate symbols: (C0603L); part number: CAP_SM-1000PF,200V,5,E012699,C0603; tolerance: 5
C158 = CAP: User Part Number: UPN; Tolerance: 10; alternate symbols: (C0603L); part number: CAP_SM-4.7UF,35V,10,E039350,C0603; tolerance: 10
C166 C168 = CAP: User Part Number: UPN; Tolerance: 5; alternate symbols: (C0402L); part number: CAP_SM-27PF,50V,5,E033384,C0402; tolerance: 5
C172 C199 C200 C233-C238 = CAP: User Part Number: UPN; Tolerance: 10; alternate symbols: (C0402L); part number: CAP_SM-0.1UF,16V,10,E018707,C0402; tolerance: 10
C179 = CAP: User Part Number: UPN; Tolerance: 10; alternate symbols: (C0402L); part number: CAP_SM-0.1UF,50V,10,E048331,C0402; tolerance: 10
C190 C203 C205 = CAP: Tolerance: 10; User Part Number: UPN; alternate symbols: (); part number: CAP_SM-10UF,50V,10,E033329,C1210-2; tolerance: 10
C191 C192 = CAP: User Part Number: UPN; Tolerance: 10; alternate symbols: (C0402L); part number: CAP_SM-0.22UF,16V,10,E035311,C0402; tolerance: 10
C193 = CAP: User Part Number: UPN; Tolerance: 0.05pF; alternate symbols: (C0402L); part number: CAP_SM-3.3PF,50V,0.05PF,E040139,C0402; tolerance: 0.05pF
C194 C197 C224 C227 C230 = CAP: Tolerance: 10; User Part Number: UPN; alternate symbols: (); part number: CAP_SM-22UF,10V,10,E030857,C1206H71; tolerance: 10
C195 = CAP: User Part Number: UPN; Tolerance: 10; alternate symbols: (C0402L); part number: CAP_SM-270PF,50V,10,E040140,C0402; tolerance: 10
C196 C198 C206 C212 C228 = CAP: Tolerance: 10; User Part Number: UPN; alternate symbols: (); part number: CAP_SM-1UF,100V,10,E044891,C1206H71; tolerance: 10
C204 = CAP: User Part Number: UPN; Tolerance: 10; alternate symbols: (C0402L); part number: CAP_SM-1500PF,50V,10,E034252,C0402; tolerance: 10
C207 = CAP: User Part Number: UPN; Tolerance: 10; alternate symbols: (C0603L); part number: CAP_SM-0.1UF,25V,10,E031923,C0603; tolerance: 10
C208 C209 = CAP: User Part Number: UPN; Tolerance: 1; alternate symbols: (C0402L); part number: CAP_SM-100PF,50V,1,E033808,C0402; tolerance: 1
C210 = CAP: User Part Number: UPN; Tolerance: 5; alternate symbols: (C0402L); part number: CAP_SM-47PF,50V,5,E011821,C0402; tolerance: 5
C211 C213 C214 C216 C217 C219 C221 C223 C226 = CAP: Tolerance: 10; User Part Number: UPN; alternate symbols: (); part number: CAP_SM-47UF,25V,10,E038014,C1210H95; tolerance: 10
C220 = CAP: User Part Number: UPN; Tolerance: 0.25; alternate symbols: (C0402L); part number: CAP_SM-2.2PF,50V,0.25,E040073,C0402; tolerance: 0.25
C222 C225 C231 = CAP: Tolerance: 10; User Part Number: UPN; alternate symbols: (); part number: CAP_SM-4.7UF,35V,10,E026260,C0805H60; tolerance: 10
C232 = CAP: User Part Number: UPN; Tolerance: 10; alternate symbols: (C0402L); part number: CAP_SM-0.01UF,25V,10,E055235,C0402; tolerance: 10
D1 = DIOTVS6P_V9: User Part Number: UPN; Tolerance: N/A; alternate symbols: (); part number: DIOTVS6P_V9_SM-ESDA6V1SC6Y,5.2V,N/A,E040427,SOT23_6-3; tolerance: N/A
D15 = DIOZNR: User Part Number: UPN; Tolerance: N/A; alternate symbols: (); part number: DIOZNR_SM-ESDA25P35-1U1M,22V,N/A,E045024,DFN2_1_6X1; tolerance: N/A
D17 = DIOTVS5P_V4: User Part Number: UPN; Tolerance: N/A; alternate symbols: (); part number: DIOTVS5P_V4_SM-ESDA25W5,24V,N/A,E045025,SC70-5_A; tolerance: N/A
DS1-DS4 = DIOLED: Tolerance: N/A; User Part Number: UPN; alternate symbols: (); part number: DIOLED_SM-SML-D13FWT86C,2.1V,N/A,E040424,LED0603-2; tolerance: N/A
DS5 DS6 = DIOLED: User Part Number: UPN; Tolerance: N/A; alternate symbols: (); part number: DIOLED_SM-SML-D14U2WT86C,2V,N/A,E040428,LED0603_A; tolerance: N/A
DS7 DS8 = DIOLED: Tolerance: N/A; User Part Number: UPN; alternate symbols: (); part number: DIOLED_SM-LY L296-Q2R2-26-Z,2V,N/A,E027232,LED0603-2; tolerance: N/A
E1 = FERRITE: Tolerance: 25; User Part Number: UPN; alternate symbols: (L1206L); part number: FERRITE_SM-600OHM,25,E019012,L1206; tolerance: 25
FL1-FL3 = FLTR3P: Tolerance: -4; User Part Number: UPN; alternate symbols: (); part number: FLTR3P_SM-4700PF,E011145,F2606; tolerance: -4
J1-J3 = CN100P_V2: Tolerance: N/A; User Part Number: UPN; alternate symbols: (); part number: CN100P_V2_SM-LSS-150-01-L-DV-A-K,E035696,CNSAMTECLSS-150-01-X-DV-A; tolerance: N/A
JP1 = CN3P: User Part Number: UPN; Tolerance: N/A; alternate symbols: (); part number: CN3P_SM-TSM-103-01-H-SV,E044652,CNSMMHDR1X3L300W100H403; tolerance: N/A
L1 = IND: User Part Number: UPN; Tolerance: 20; alternate symbols: (); part number: IND_SM-10UH,20,E028516,L1210H67; tolerance: 20
L2 = IND: User Part Number: UPN; Tolerance: 20; alternate symbols: (); part number: IND_SM-0.1UH,20,E046177,LSMSQ157H122; tolerance: 20
L3 = IND: Tolerance: 20; User Part Number: UPN; alternate symbols: (); part number: IND_SM-1UH,20,E018077,LSML208W216H122; tolerance: 20
L4 = IND: User Part Number: UPN; Tolerance: 20; alternate symbols: (); part number: IND_SM-220NH,20,E032809,LSMSQ157H83_A; tolerance: 20
P1 = CN24PAB_2GND_6SHLD: Tolerance: N/A; User Part Number: UPN; alternate symbols: (); part number: CN24PAB_2GND_6SHLD_TH-632723300011,E043638,CNWURTH632723300011; tolerance: N/A
P6 = CN10P_ODD_EVEN: User Part Number: UPN; Tolerance: N/A; alternate symbols: (); part number: CN10P_ODD_EVEN_TH-SHF-105-01-L-D-TH-TR,E027236,CNTHMHDR2X5L500W200H215; tolerance: N/A
R1 = RES: User Part Number: UPN; Tolerance: 1; alternate symbols: (R0402L); part number: RES_SM-34,E040037,1/10W,1,R0402; tolerance: 1
R2 = RES: User Part Number: UPN; Tolerance: 1; alternate symbols: (R0402L,R0402L_ALT); part number: RES_SM-2K,E003752,1/10W,1,R0402; tolerance: 1
R3 = RES: User Part Number: UPN; Tolerance: 0.5; alternate symbols: (R0402L); part number: RES_SM-200,E022007,1/16W,0.5,R0402; tolerance: 0.5
R4 = RES: User Part Number: UPN; Tolerance: 1; alternate symbols: (R0402L,R0402L_ALT); part number: RES_SM-240,E010877,1/10W,1,R0402; tolerance: 1
R5 R7 R16 R18 R27 R41-R45 R58 R68 R69 R85 R111 R112 R114-R120 = RES: User Part Number: UPN; Tolerance: JUMPER; alternate symbols: (R0402L); part number: RES_SM-0,E030866,1/5W,JUMPER,R0402; tolerance: JUMPER
R6 R66 = RES: User Part Number: UPN; Tolerance: 0.1; alternate symbols: (R0402L); part number: RES_SM-5.1K,E010267,1/16W,0.1,R0402; tolerance: 0.1
R8 R23-R26 R46-R48 R50 R51 R57 R60-R64 R70 R71 R75 R78 R79 R86 R87 R113 R124 R139 R140 R143 = RES: User Part Number: UPN; Tolerance: 1; alternate symbols: (R0402L,R0402L_ALT); part number: RES_SM-10K,E003751,1/10W,1,R0402; tolerance: 1
R9-R11 = RES: User Part Number: UPN; Tolerance: 1; alternate symbols: (R0402L,R0402L_ALT); part number: RES_SM-1K,E003763,1/10W,1,R0402; tolerance: 1
R12 R13 R29 R30 = RES: User Part Number: UPN; Tolerance: 1; alternate symbols: (R0402L); part number: RES_SM-100,E016329,1/10W,1,R0402; tolerance: 1
R14 R15 R31 R32 = RES: User Part Number: UPN; Tolerance: 5; alternate symbols: (R0402L); part number: RES_SM-2.2K,E003446,1/10W,5,R0402; tolerance: 5
R17 = RES: User Part Number: UPN; Tolerance: 1; alternate symbols: (R0402L); part number: RES_SM-20,E020520,1/10W,1,R0402; tolerance: 1
R19 R21 R33-R35 R37 R38 R53 R55 R81-R84 = RES: User Part Number: UPN; Tolerance: 5; alternate symbols: (R0402L); part number: RES_SM-100K,E027220,1/16W,5,R0402; tolerance: 5
R20 = RES: User Part Number: UPN; Tolerance: 1; alternate symbols: (R0402L,R0402L_ALT); part number: RES_SM-1.2K,E007439,1/10W,1,R0402; tolerance: 1
R22 = RES: User Part Number: UPN; Tolerance: 1; alternate symbols: (R0402L); part number: RES_SM-499K,E019889,1/10W,1,R0402; tolerance: 1
R36 R54 R56 = RES: User Part Number: UPN; Tolerance: 1; alternate symbols: (R0402L,R0402L_ALT); part number: RES_SM-20K,E003791,1/10W,1,R0402; tolerance: 1
R39 R40 R67 R121 R122 = RES: User Part Number: UPN; Tolerance: 1; alternate symbols: (R0402L); part number: RES_SM-10K,E056162,1/10W,1,R0402; tolerance: 1
R49 R52 R110 R123 R141 R142 R144 = RES: User Part Number: UPN; Tolerance: 5; alternate symbols: (R0402L); part number: RES_SM-33,E003452,1/10W,5,R0402; tolerance: 5
R59 R72-R74 R76 R77 R89 R90 = RES: User Part Number: UPN; Tolerance: 1; alternate symbols: (R0402L,R0402L_ALT); part number: RES_SM-330,E021894,1/16W,1,R0402; tolerance: 1
R65 = RES: User Part Number: UPN; Tolerance: 1; alternate symbols: (R0402L); part number: RES_SM-22.1K,E007152,1/16W,1,R0402; tolerance: 1
R80 = RES: User Part Number: UPN; Tolerance: 1; alternate symbols: (R0603L); part number: RES_SM-1MEG,E030873,1/10W,1,R0603; tolerance: 1
R88 = RES: User Part Number: UPN; Tolerance: 1; alternate symbols: (R0402L); part number: RES_SM-47.5K,E013598,1/10W,1,R0402; tolerance: 1
R91 = RES: User Part Number: UPN; Tolerance: 1; alternate symbols: (R0402L); part number: RES_SM-37.4K,E017173,1/10W,1,R0402; tolerance: 1
R92-R94 = RES: User Part Number: UPN; Tolerance: JUMPER; alternate symbols: (R0402L,R0402L_ALT); part number: RES_SM-0,E003438,1/10W,JUMPER,R0402; tolerance: JUMPER
R95 = RES: User Part Number: UPN; Tolerance: 1; alternate symbols: (R0402L); part number: RES_SM-38.3K,E016739,1/10W,1,R0402; tolerance: 1
R96 R99-R101 R104 R105 R107 R108 = RES: User Part Number: UPN; Tolerance: 1; alternate symbols: (R0402L,R0402L_ALT); part number: RES_SM-100K,E003796,1/10W,1,R0402; tolerance: 1
R97 = RES: User Part Number: UPN; Tolerance: 1; alternate symbols: (R0402L); part number: RES_SM-1.69MEG,E038133,1/16W,1,R0402; tolerance: 1
R98 = RES: User Part Number: UPN; Tolerance: 0.1; alternate symbols: (R0402L); part number: RES_SM-15.8K,E023709,1/16W,0.1,R0402; tolerance: 0.1
R102 = RES: User Part Number: UPN; Tolerance: 0.1; alternate symbols: (R0402L); part number: RES_SM-91K,E041184,1/16W,0.1,R0402; tolerance: 0.1
R103 = RES: User Part Number: UPN; Tolerance: 0.1; alternate symbols: (R0805L); part number: RES_SM-9K,E029209,1/8W,0.1,R0805; tolerance: 0.1
R106 = RES: User Part Number: UPN; Tolerance: 1; alternate symbols: (R0402L); part number: RES_SM-41.2K,E022008,1/10W,1,R0402; tolerance: 1
R109 = RES: User Part Number: UPN; Tolerance: 1; alternate symbols: (R0402L); part number: RES_SM-56.2K,E003771,1/10W,1,R0402; tolerance: 1
R136 R137 = RES: User Part Number: UPN; Tolerance: 1; alternate symbols: (R0402L,R0402L_ALT); part number: RES_SM-3.3K,E010034,1/10W,1,R0402; tolerance: 1
RN1-RN7 = RESNET_8P_4R_V4: Tolerance: 5; User Part Number: UPN; alternate symbols: (); part number: RESNET_8P_4R_V4_SM-100,E046239,0.063W,5,RESNET8; tolerance: 5
S1 = SWBCDROTARY6P: User Part Number: UPN; Tolerance: N/A; alternate symbols: (); part number: SWBCDROTARY6P_SM-RDTAR10S1R,E040089,SWSMSQ394H268; tolerance: N/A
S2 = SWSPST4PIN_GND: Tolerance: N/A; User Part Number: UPN; alternate symbols: (); part number: SWSPST4PIN_GND_SM-KMR223GLFG,E040082,SWSML165W110H75-G; tolerance: N/A
TP1-TP4 = CNTP1P: User Part Number: UPN; Tolerance: N/A; alternate symbols: (); part number: CNTP1P_TH-WHT,E000946,CNLOOPTP; tolerance: N/A
U1 = ADSP_21835: User Part Number: UPN; Tolerance: N/A; alternate symbols: (); part number: ADSP_21835_SM-ADSP-21835-BPZENG,E058333,CSPBGA400_17X17; tolerance: N/A
U2 = ICMIC5166: Tolerance: N/A; User Part Number: UPN; alternate symbols: (); part number: ICMIC5166_SM-MIC5166YML-TR,E050642,DFN10_3X3_PAD2_4X1_7; tolerance: N/A
U3 U5 U9 U10 U19-U21 = 741G125: User Part Number: UPN; Tolerance: N/A; alternate symbols: (); part number: 741G125_SM-74CBTLV1G125DBVRQ1,E040081,SOT23-5L-2; tolerance: N/A
U4 = ICIS25XP512M: User Part Number: UPN; Tolerance: N/A; alternate symbols: (); part number: ICIS25XP512M_SM-IS25LP512M-RHLE,E054395,TBGA24; tolerance: N/A
U7 = CMOSPI3C3125: Tolerance: N/A; User Part Number: UPN; alternate symbols: (); part number: CMOSPI3C3125_SM-PI3C3125LEX,E040333,TSSOP14; tolerance: N/A
U8 = ICIS4XTR16256: User Part Number: UPN; Tolerance: N/A; alternate symbols: (); part number: ICIS4XTR16256_SM-IS43TR16256BL-107MBL,E057159,BGA96_13X9; tolerance: N/A
U11 U13 = 7408_V3: User Part Number: UPN; Tolerance: N/A; alternate symbols: (); part number: 7408_V3_SM-SN74LVC1G08QDBVRQ1,E040048,SOT23-5L-2; tolerance: N/A
U14 = ADM6315: User Part Number: UPN; Tolerance: N/A; alternate symbols: (); part number: ADM6315_SM-ADM6315-29D2ARTZR7,E027659,SOT143A; tolerance: N/A
U15 = ICCP2102NA: User Part Number: UPN; Tolerance: N/A; alternate symbols: (); part number: ICCP2102NA_SM-CP2102N-A02-GQFN28,E050004,QFN28_5X5_PAD3_5X3_5; tolerance: N/A
U16 = ADLTC3310: User Part Number: UPN; Tolerance: N/A; alternate symbols: (); part number: ADLTC3310_SM-LTC3310JV#WPBF,E045269,QFN18_3X3_PAD1_51X1_7; tolerance: N/A
U17 = ADLTC3307: User Part Number: UPN; Tolerance: N/A; alternate symbols: (); part number: ADLTC3307_SM-LTC3307AHV#WTRMPBF,E042057,QFN12_2X2_PAD0_7X0_7; tolerance: N/A
U18 = ADP120_V2: User Part Number: UPN; Tolerance: N/A; alternate symbols: (); part number: ADP120_V2_SM-ADP151AUJZ-1.8-R7,E013337,TSOT-5; tolerance: N/A
U22 U23 U27-U30 = CMOSSN74CB3T3125: Tolerance: N/A; User Part Number: UPN; alternate symbols: (); part number: CMOSSN74CB3T3125_SM-SN74CB3T3125RGYR,E050248,QFN14_3_5X3_5_PAD2_05X2_05; tolerance: N/A
U24 = ADP5587: Tolerance: N/A; User Part Number: UPN; alternate symbols: (); part number: ADP5587_SM-ADP5587ACPZ-1,E018893,QFN24_4X4_PAD2_1X2_1; tolerance: N/A
U25 = ICS71KLXXX: Tolerance: N/A; User Part Number: UPN; alternate symbols: (); part number: ICS71KLXXX_SM-S71KL512SC0BHB003,E050383,BGA24_8X6; tolerance: N/A
U26 = IC24XX01: User Part Number: UPN; Tolerance: N/A; alternate symbols: (); part number: IC24XX01_SM-24AA01T-I/OT,E035648,SOT23-5L-2; tolerance: N/A
VR1 = ADLT8636: User Part Number: UPN; Tolerance: N/A; alternate symbols: (); part number: ADLT8636_SM-LT8636EV#WPBF,E041170,LQFN20_4X3_PAD2_65X1_65; tolerance: N/A
Y1 = XTAL4PIN_V5: Tolerance: 20PPM; User Part Number: UPN; alternate symbols: (); part number: XTAL4PIN_V5_SM-25MEGHZ,E050382,YSML126W98H31; tolerance: 20PPM
Y2 = XTALOSC4P_V2: Tolerance: N/A; User Part Number: UPN; alternate symbols: (); part number: XTALOSC4P_V2_SM-25MEGHZ,E057580,YSML79W63H32; tolerance: N/A
Y4 = XTALOSC4P_V18: Tolerance: N/A; User Part Number: UPN; alternate symbols: (); part number: XTALOSC4P_V18_SM-24.576MEGHZ,E049327,YSML79W63H31; tolerance: N/A
Y5 Y6 = XTALOSC4P_V2: Tolerance: N/A; User Part Number: UPN; alternate symbols: (); part number: XTALOSC4P_V2_SM-25MEGHZ,E032840,YSML98W79H35; tolerance: N/A

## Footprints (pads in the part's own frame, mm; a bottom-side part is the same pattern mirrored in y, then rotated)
BGA24_8X6
  round 0.305 smd: A2(-2,-1) A3(-2,0) A4(-2,1) A5(-2,2) B1(-1,-2) B2(-1,-1) B3(-1,0) B4(-1,1) B5(-1,2) C1(0,-2) C2(0,-1) C3(0,0) C4(0,1) C5(0,2) D1(1,-2) D2(1,-1) D3(1,0) D4(1,1) D5(1,2) E1(2,-2) E2(2,-1) E3(2,0) E4(2,1) E5(2,2)
BGA96_13X9
  round 0.356 smd: A1(-6,-3.2) A2(-6,-2.4) A3(-6,-1.6) A7(-6,1.6) A8(-6,2.4) A9(-6,3.2) B1(-5.2,-3.2) B2(-5.2,-2.4) B3(-5.2,-1.6) B7(-5.2,1.6) B8(-5.2,2.4) B9(-5.2,3.2) C1(-4.4,-3.2) C2(-4.4,-2.4) C3(-4.4,-1.6) C7(-4.4,1.6) C8(-4.4,2.4) C9(-4.4,3.2) D1(-3.6,-3.2) D2(-3.6,-2.4) D3(-3.6,-1.6) D7(-3.6,1.6) D8(-3.6,2.4) D9(-3.6,3.2) E1(-2.8,-3.2) E2(-2.8,-2.4) E3(-2.8,-1.6) E7(-2.8,1.6) E8(-2.8,2.4) E9(-2.8,3.2) F1(-2,-3.2) F2(-2,-2.4) F3(-2,-1.6) F7(-2,1.6) F8(-2,2.4) F9(-2,3.2) G1(-1.2,-3.2) G2(-1.2,-2.4) G3(-1.2,-1.6) G7(-1.2,1.6) G8(-1.2,2.4) G9(-1.2,3.2) H1(-0.4,-3.2) H2(-0.4,-2.4) H3(-0.4,-1.6) H7(-0.4,1.6) H8(-0.4,2.4) H9(-0.4,3.2) J1(0.4,-3.2) J2(0.4,-2.4) J3(0.4,-1.6) J7(0.4,1.6) J8(0.4,2.4) J9(0.4,3.2) K1(1.2,-3.2) K2(1.2,-2.4) K3(1.2,-1.6) K7(1.2,1.6) K8(1.2,2.4) K9(1.2,3.2) L1(2,-3.2) L2(2,-2.4) L3(2,-1.6) L7(2,1.6) L8(2,2.4) L9(2,3.2) M1(2.8,-3.2) M2(2.8,-2.4) M3(2.8,-1.6) M7(2.8,1.6) M8(2.8,2.4) M9(2.8,3.2) N1(3.6,-3.2) N2(3.6,-2.4) N3(3.6,-1.6) N7(3.6,1.6) N8(3.6,2.4) N9(3.6,3.2) P1(4.4,-3.2) P2(4.4,-2.4) P3(4.4,-1.6) P7(4.4,1.6) P8(4.4,2.4) P9(4.4,3.2) R1(5.2,-3.2) R2(5.2,-2.4) R3(5.2,-1.6) R7(5.2,1.6) R8(5.2,2.4) R9(5.2,3.2) T1(6,-3.2) T2(6,-2.4) T3(6,-1.6) T7(6,1.6) T8(6,2.4) T9(6,3.2)
C0201
  rect 0.305x0.406 smd: 1(-0.318,0) 2(0.318,0)
C0402
  rect 0.584x0.66 smd: 1(-0.5,0) 2(0.5,0)
C0603
  rect 0.94x0.991 smd: 1(-0.8,0) 2(0.8,0)
C0805H55
  rect 1.143x1.448 smd: 1(-0.9,0) 2(0.9,0)
C0805H60
  rect 1.295x1.6 smd: 1(-0.953,0) 2(0.953,0)
C1206H71
  rect 1.6x2.007 smd: 1(-1.397,0) 2(1.397,0)
C1210-2
  rect 1.575x2.692 smd: 1(-1.397,0) 2(1.397,0)
C1210H95
  rect 1.575x2.692 smd: 1(-1.397,0) 2(1.397,0)
C1210H106
  rect 1.092x2.057 smd: 1(-1.646,0) 2(1.646,0)
CNLOOPTP
  round 2.159 hole 1.6: 1(0,0)
CNSAMTECLSS-150-01-X-DV-A
  round 1.016 hole 0.889 unplated: (-16.625,-1.1) (16.625,-1.1)
  rect 0.406x1.6 smd: 1(-15.557,1.8) 2(-15.557,-1.8) 3(-14.922,1.8) 4(-14.922,-1.8) 5(-14.287,1.8) 6(-14.287,-1.8) 7(-13.652,1.8) 8(-13.652,-1.8) 9(-13.018,1.8) 10(-13.018,-1.8) 11(-12.383,1.8) 12(-12.383,-1.8) 13(-11.748,1.8) 14(-11.748,-1.8) 15(-11.113,1.8) 16(-11.113,-1.8) 17(-10.477,1.8) 18(-10.477,-1.8) 19(-9.842,1.8) 20(-9.842,-1.8) 21(-9.207,1.8) 22(-9.207,-1.8) 23(-8.572,1.8) 24(-8.572,-1.8) 25(-7.938,1.8) 26(-7.938,-1.8) 27(-7.303,1.8) 28(-7.303,-1.8) 29(-6.668,1.8) 30(-6.668,-1.8) 31(-6.032,1.8) 32(-6.032,-1.8) 33(-5.397,1.8) 34(-5.397,-1.8) 35(-4.763,1.8) 36(-4.763,-1.8) 37(-4.128,1.8) 38(-4.128,-1.8) 39(-3.493,1.8) 40(-3.493,-1.8) 41(-2.857,1.8) 42(-2.857,-1.8) 43(-2.223,1.8) 44(-2.223,-1.8) 45(-1.587,1.8) 46(-1.587,-1.8) 47(-0.953,1.8) 48(-0.953,-1.8) 49(-0.318,1.8) 50(-0.318,-1.8) 51(0.318,1.8) 52(0.318,-1.8) 53(0.953,1.8) 54(0.953,-1.8) 55(1.587,1.8) 56(1.587,-1.8) 57(2.223,1.8) 58(2.223,-1.8) 59(2.857,1.8) 60(2.857,-1.8) 61(3.493,1.8) 62(3.493,-1.8) 63(4.128,1.8) 64(4.128,-1.8) 65(4.763,1.8) 66(4.763,-1.8) 67(5.397,1.8) 68(5.397,-1.8) 69(6.032,1.8) 70(6.032,-1.8) 71(6.668,1.8) 72(6.668,-1.8) 73(7.303,1.8) 74(7.303,-1.8) 75(7.938,1.8) 76(7.938,-1.8) 77(8.572,1.8) 78(8.572,-1.8) 79(9.207,1.8) 80(9.207,-1.8) 81(9.842,1.8) 82(9.842,-1.8) 83(10.477,1.8) 84(10.477,-1.8) 85(11.113,1.8) 86(11.113,-1.8) 87(11.748,1.8) 88(11.748,-1.8) 89(12.383,1.8) 90(12.383,-1.8) 91(13.018,1.8) 92(13.018,-1.8) 93(13.652,1.8) 94(13.652,-1.8) 95(14.287,1.8) 96(14.287,-1.8) 97(14.922,1.8) 98(14.922,-1.8) 99(15.557,1.8) 100(15.557,-1.8)
CNSMMHDR1X3L300W100H403
  rect 1.27x3.429 smd: 1(-2.54,1.46) 2(0,-1.46) 3(2.54,1.46)
CNTHMHDR2X5L500W200H215
  rect 1.143x1.143 hole 0.737: 1(0,0)
  round 1.143 hole 0.737: 2(0,1.27) 3(1.27,0) 4(1.27,1.27) 5(2.54,0) 6(2.54,1.27) 7(3.81,0) 8(3.81,1.27) 9(5.08,0) 10(5.08,1.27)
CNWURTH632723300011
  rect 0.305x1.194 smd: A1(-2.75,4.577) A2(-2.25,4.577) A3(-1.75,4.577) A4(-1.25,4.577) A5(-0.75,4.577) A6(-0.25,4.577) A7(0.25,4.577) A8(0.75,4.577) A9(1.25,4.577) A10(1.75,4.577) A11(2.25,4.577) A12(2.75,4.577)
  round 0.66 hole 0.406: B1(2.8,3.33) B2(2.4,2.63) B3(1.6,2.63) B4(1.2,3.33) B5(0.8,2.63) B6(0.4,3.33) B7(-0.4,3.33) B8(-0.8,2.63) B9(-1.2,3.33) B10(-1.6,2.63) B11(-2.4,2.63) B12(-2.8,3.33) GND1(-2,3.33) GND2(2,3.33)
  oval 0.991x1.6 hole 0.61x1.219: SH1(-4.27,2.18) SH2(4.27,2.18) SH3(4.27,-2.55) SH4(-4.27,-2.55)
  rect 0.203x0.991 smd: SH5(0,-0.005) SH6(0,-3.105)
CSPBGA400_17X17
  round 0.356 smd: A1(-7.6,-7.6) A2(-7.6,-6.8) A3(-7.6,-6) A4(-7.6,-5.2) A5(-7.6,-4.4) A6(-7.6,-3.6) A7(-7.6,-2.8) A8(-7.6,-2) A9(-7.6,-1.2) A10(-7.6,-0.4) A11(-7.6,0.4) A12(-7.6,1.2) A13(-7.6,2) A14(-7.6,2.8) A15(-7.6,3.6) A16(-7.6,4.4) A17(-7.6,5.2) A18(-7.6,6) A19(-7.6,6.8) A20(-7.6,7.6) B1(-6.8,-7.6) B2(-6.8,-6.8) B3(-6.8,-6) B4(-6.8,-5.2) B5(-6.8,-4.4) B6(-6.8,-3.6) B7(-6.8,-2.8) B8(-6.8,-2) B9(-6.8,-1.2) B10(-6.8,-0.4) B11(-6.8,0.4) B12(-6.8,1.2) B13(-6.8,2) B14(-6.8,2.8) B15(-6.8,3.6) B16(-6.8,4.4) B17(-6.8,5.2) B18(-6.8,6) B19(-6.8,6.8) B20(-6.8,7.6) C1(-6,-7.6) C2(-6,-6.8) C3(-6,-6) C4(-6,-5.2) C5(-6,-4.4) C6(-6,-3.6) C7(-6,-2.8) C8(-6,-2) C9(-6,-1.2) C10(-6,-0.4) C11(-6,0.4) C12(-6,1.2) C13(-6,2) C14(-6,2.8) C15(-6,3.6) C16(-6,4.4) C17(-6,5.2) C18(-6,6) C19(-6,6.8) C20(-6,7.6) D1(-5.2,-7.6) D2(-5.2,-6.8) D3(-5.2,-6) D4(-5.2,-5.2) D5(-5.2,-4.4) D6(-5.2,-3.6) D7(-5.2,-2.8) D8(-5.2,-2) D9(-5.2,-1.2) D10(-5.2,-0.4) D11(-5.2,0.4) D12(-5.2,1.2) D13(-5.2,2) D14(-5.2,2.8) D15(-5.2,3.6) D16(-5.2,4.4) D17(-5.2,5.2) D18(-5.2,6) D19(-5.2,6.8) D20(-5.2,7.6) E1(-4.4,-7.6) E2(-4.4,-6.8) E3(-4.4,-6) E4(-4.4,-5.2) E5(-4.4,-4.4) E6(-4.4,-3.6) E7(-4.4,-2.8) E8(-4.4,-2) E9(-4.4,-1.2) E10(-4.4,-0.4) E11(-4.4,0.4) E12(-4.4,1.2) E13(-4.4,2) E14(-4.4,2.8) E15(-4.4,3.6) E16(-4.4,4.4) E17(-4.4,5.2) E18(-4.4,6) E19(-4.4,6.8) E20(-4.4,7.6) F1(-3.6,-7.6) F2(-3.6,-6.8) F3(-3.6,-6) F4(-3.6,-5.2) F5(-3.6,-4.4) F6(-3.6,-3.6) F7(-3.6,-2.8) F8(-3.6,-2) F9(-3.6,-1.2) F10(-3.6,-0.4) F11(-3.6,0.4) F12(-3.6,1.2) F13(-3.6,2) F14(-3.6,2.8) F15(-3.6,3.6) F16(-3.6,4.4) F17(-3.6,5.2) F18(-3.6,6) F19(-3.6,6.8) F20(-3.6,7.6) G1(-2.8,-7.6) G2(-2.8,-6.8) G3(-2.8,-6) G4(-2.8,-5.2) G5(-2.8,-4.4) G6(-2.8,-3.6) G7(-2.8,-2.8) G8(-2.8,-2) G9(-2.8,-1.2) G10(-2.8,-0.4) G11(-2.8,0.4) G12(-2.8,1.2) G13(-2.8,2) G14(-2.8,2.8) G15(-2.8,3.6) G16(-2.8,4.4) G17(-2.8,5.2) G18(-2.8,6) G19(-2.8,6.8) G20(-2.8,7.6) H1(-2,-7.6) H2(-2,-6.8) H3(-2,-6) H4(-2,-5.2) H5(-2,-4.4) H6(-2,-3.6) H7(-2,-2.8) H8(-2,-2) H9(-2,-1.2) H10(-2,-0.4) H11(-2,0.4) H12(-2,1.2) H13(-2,2) H14(-2,2.8) H15(-2,3.6) H16(-2,4.4) H17(-2,5.2) H18(-2,6) H19(-2,6.8) H20(-2,7.6) J1(-1.2,-7.6) J2(-1.2,-6.8) J3(-1.2,-6) J4(-1.2,-5.2) J5(-1.2,-4.4) J6(-1.2,-3.6) J7(-1.2,-2.8) J8(-1.2,-2) J9(-1.2,-1.2) J10(-1.2,-0.4) J11(-1.2,0.4) J12(-1.2,1.2) J13(-1.2,2) J14(-1.2,2.8) J15(-1.2,3.6) J16(-1.2,4.4) J17(-1.2,5.2) J18(-1.2,6) J19(-1.2,6.8) J20(-1.2,7.6) K1(-0.4,-7.6) K2(-0.4,-6.8) K3(-0.4,-6) K4(-0.4,-5.2) K5(-0.4,-4.4) K6(-0.4,-3.6) K7(-0.4,-2.8) K8(-0.4,-2) K9(-0.4,-1.2) K10(-0.4,-0.4) K11(-0.4,0.4) K12(-0.4,1.2) K13(-0.4,2) K14(-0.4,2.8) K15(-0.4,3.6) K16(-0.4,4.4) K17(-0.4,5.2) K18(-0.4,6) K19(-0.4,6.8) K20(-0.4,7.6) L1(0.4,-7.6) L2(0.4,-6.8) L3(0.4,-6) L4(0.4,-5.2) L5(0.4,-4.4) L6(0.4,-3.6) L7(0.4,-2.8) L8(0.4,-2) L9(0.4,-1.2) L10(0.4,-0.4) L11(0.4,0.4) L12(0.4,1.2) L13(0.4,2) L14(0.4,2.8) L15(0.4,3.6) L16(0.4,4.4) L17(0.4,5.2) L18(0.4,6) L19(0.4,6.8) L20(0.4,7.6) M1(1.2,-7.6) M2(1.2,-6.8) M3(1.2,-6) M4(1.2,-5.2) M5(1.2,-4.4) M6(1.2,-3.6) M7(1.2,-2.8) M8(1.2,-2) M9(1.2,-1.2) M10(1.2,-0.4) M11(1.2,0.4) M12(1.2,1.2) M13(1.2,2) M14(1.2,2.8) M15(1.2,3.6) M16(1.2,4.4) M17(1.2,5.2) M18(1.2,6) M19(1.2,6.8) M20(1.2,7.6) N1(2,-7.6) N2(2,-6.8) N3(2,-6) N4(2,-5.2) N5(2,-4.4) N6(2,-3.6) N7(2,-2.8) N8(2,-2) N9(2,-1.2) N10(2,-0.4) N11(2,0.4) N12(2,1.2) N13(2,2) N14(2,2.8) N15(2,3.6) N16(2,4.4) N17(2,5.2) N18(2,6) N19(2,6.8) N20(2,7.6) P1(2.8,-7.6) P2(2.8,-6.8) P3(2.8,-6) P4(2.8,-5.2) P5(2.8,-4.4) P6(2.8,-3.6) P7(2.8,-2.8) P8(2.8,-2) P9(2.8,-1.2) P10(2.8,-0.4) P11(2.8,0.4) P12(2.8,1.2) P13(2.8,2) P14(2.8,2.8) P15(2.8,3.6) P16(2.8,4.4) P17(2.8,5.2) P18(2.8,6) P19(2.8,6.8) P20(2.8,7.6) R1(3.6,-7.6) R2(3.6,-6.8) R3(3.6,-6) R4(3.6,-5.2) R5(3.6,-4.4) R6(3.6,-3.6) R7(3.6,-2.8) R8(3.6,-2) R9(3.6,-1.2) R10(3.6,-0.4) R11(3.6,0.4) R12(3.6,1.2) R13(3.6,2) R14(3.6,2.8) R15(3.6,3.6) R16(3.6,4.4) R17(3.6,5.2) R18(3.6,6) R19(3.6,6.8) R20(3.6,7.6) T1(4.4,-7.6) T2(4.4,-6.8) T3(4.4,-6) T4(4.4,-5.2) T5(4.4,-4.4) T6(4.4,-3.6) T7(4.4,-2.8) T8(4.4,-2) T9(4.4,-1.2) T10(4.4,-0.4) T11(4.4,0.4) T12(4.4,1.2) T13(4.4,2) T14(4.4,2.8) T15(4.4,3.6) T16(4.4,4.4) T17(4.4,5.2) T18(4.4,6) T19(4.4,6.8) T20(4.4,7.6) U1(5.2,-7.6) U2(5.2,-6.8) U3(5.2,-6) U4(5.2,-5.2) U5(5.2,-4.4) U6(5.2,-3.6) U7(5.2,-2.8) U8(5.2,-2) U9(5.2,-1.2) U10(5.2,-0.4) U11(5.2,0.4) U12(5.2,1.2) U13(5.2,2) U14(5.2,2.8) U15(5.2,3.6) U16(5.2,4.4) U17(5.2,5.2) U18(5.2,6) U19(5.2,6.8) U20(5.2,7.6) V1(6,-7.6) V2(6,-6.8) V3(6,-6) V4(6,-5.2) V5(6,-4.4) V6(6,-3.6) V7(6,-2.8) V8(6,-2) V9(6,-1.2) V10(6,-0.4) V11(6,0.4) V12(6,1.2) V13(6,2) V14(6,2.8) V15(6,3.6) V16(6,4.4) V17(6,5.2) V18(6,6) V19(6,6.8) V20(6,7.6) W1(6.8,-7.6) W2(6.8,-6.8) W3(6.8,-6) W4(6.8,-5.2) W5(6.8,-4.4) W6(6.8,-3.6) W7(6.8,-2.8) W8(6.8,-2) W9(6.8,-1.2) W10(6.8,-0.4) W11(6.8,0.4) W12(6.8,1.2) W13(6.8,2) W14(6.8,2.8) W15(6.8,3.6) W16(6.8,4.4) W17(6.8,5.2) W18(6.8,6) W19(6.8,6.8) W20(6.8,7.6) Y1(7.6,-7.6) Y2(7.6,-6.8) Y3(7.6,-6) Y4(7.6,-5.2) Y5(7.6,-4.4) Y6(7.6,-3.6) Y7(7.6,-2.8) Y8(7.6,-2) Y9(7.6,-1.2) Y10(7.6,-0.4) Y11(7.6,0.4) Y12(7.6,1.2) Y13(7.6,2) Y14(7.6,2.8) Y15(7.6,3.6) Y16(7.6,4.4) Y17(7.6,5.2) Y18(7.6,6) Y19(7.6,6.8) Y20(7.6,7.6)
DFN2_1_6X1
  rect 0.508x0.787 smd: A(0.604,0) C(-0.604,0)
DFN10_3X3_PAD2_4X1_7
  oval 0.279x0.711 smd: 1(-1,-1.406) 2(-0.5,-1.406) 3(0,-1.406) 4(0.5,-1.406) 5(1,-1.406) 6(1,1.406) 7(0.5,1.406) 8(0,1.406) 9(-0.5,1.406) 10(-1,1.406)
  rect 2.388x1.702 smd: PAD(0,0)
F2606
  rect 1.651x1.651 smd: 1(-3.35,0) 3(3.35,0)
  rect 2.591x2.591 smd: 2(0,0)
L1206
  rect 1.524x1.575 smd: 1(-1.714,0) 2(1.714,0)
L1210H67
  rect 1.245x2.007 smd: 1(-1.272,0) 2(1.272,0)
LED0603-2
  rect 0.787x0.787 smd: A(0.787,0) C(-0.787,0)
LED0603_A
  rect 0.889x0.787 smd: A(0.845,0) C(-0.845,0)
LQFN20_4X3_PAD2_65X1_65
  rect 0.381x0.381 smd: (-1.809,1.31) (-1.809,-1.31) (1.809,1.31) (1.809,-1.31)
  oval 0.279x0.737 smd: 1(-1.25,-1.393) 2(-0.75,-1.393) 3(-0.25,-1.393) 4(0.25,-1.393) 5(0.75,-1.393) 6(1.25,-1.393) 11(1.25,1.393) 12(0.75,1.393) 13(0.25,1.393) 14(-0.25,1.393) 15(-0.75,1.393) 16(-1.25,1.393)
  oval 0.737x0.279 smd: 7(1.893,-0.75) 8(1.893,-0.25) 9(1.893,0.25) 10(1.893,0.75) 17(-1.893,0.75) 18(-1.893,0.25) 19(-1.893,-0.25) 20(-1.893,-0.75)
  rect 2.642x1.651 smd: PAD(0,0)
